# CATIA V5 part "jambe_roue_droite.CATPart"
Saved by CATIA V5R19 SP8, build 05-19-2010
Part number: jambe_roue_droite
Bounding box of the stored display mesh (mm): x 615 to 975, y -524.989 to 900, z -644.15 to 166.768
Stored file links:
  G:\EU_thinkMotion\CFAO_2010\MMS_groupe2\MMS_groupe2\OK\mmartini\mmartiniCFAO\jambe_roue_droite.CATPart
  C:\Users\Mathieu Martini\Desktop\CFAO\Animation\CFAO.CATProduct
  G:\EU_thinkMotion\CFAO_2010\MMS_groupe2\MMS_groupe2\OK\mmartini\mmartiniCFAO\Squelette.CATPart
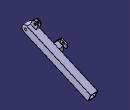
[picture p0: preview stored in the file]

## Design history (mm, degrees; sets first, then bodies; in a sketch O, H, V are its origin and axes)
External parameters (linked from other documents)
  External.diametre_canon = 150 mm
  External.diametre_verin = 120 mm
AxisSystem1: origin (0, 0, 0), X (1, 0, 0), Y (0, 1, 0), Z (0, 0, 1)
Set1
  Sketch1 on Plane1, origin (825, 0, 0), H (0, 1, 0), V (0, 0, 1)
    axis line L1 (-516.747, 29.0949) -> (1500, -850)
    point P2 (1500, -850)
    reference projected point E1 (1500, -850) from Line1
    line L2 (-420.0311, 68.7522) -> (900, -506.646)
    point P3 (900, -506.646)
    reference projected point E2 (-450, 0) from Point2
    circle A1 centre (-450, 0) radius 24
    point P4 (-450, 0)
    reference projected point E3 (-450, 0) from Point2
    line L3 (840.0622, -644.1504) -> (-479.9689, -68.7522)
    point P5 (840.0622, -644.1504)
    arc A2 centre (-450, 0) radius 75 from (-420.0311, 68.7522) to (-479.9689, -68.7522) ccw
    point P6 (-420.0311, 68.7522)
    reference intersected line E4 through (900, 0) direction (0, 1) from Plane2
    line L4 (900, -506.646) -> (840.0622, -644.1504)
    point P9 (840.0622, -644.1504)
    distance L1 L2 = 75 {= External.diametre_canon /2}
    radius A1 = 24 {= External.diametre_verin /5}
    distance L3 L1 = 75 {= External.diametre_canon /2}
    coincidence: P2 E1, L1 E2, P4 E3, A2 P6, P6 L2, P3 E4, P9 L3, P9 P5
    tangency: A2 L2
    perpendicularity: L4 L3
Set2
  Plane1 "Plan_jambe_droite_roue": linked copy from another document
  Point1 "Point_verin_droit": linked copy from another document
  Line1 "axe_roue": linked copy from another document
  Point2: linked copy from another document
  Plane2 "Plan_berceaumax": linked copy from another document
  Plane3: linked copy from another document
  Line2 "Droite_plan_de_construction_verin": linked copy from another document
  Plane4 "Plan_verin_droit": linked copy from another document
  Point3: linked copy from another document
  Plane5: linked copy from another document
  Plane6 "Plan_rayon_ext_verin_droit": linked copy from another document
  Plane7 "Plan_rayon_int_verin_droit": linked copy from another document
  Point4: linked copy from another document
  Line3: linked copy from another document
Body1 (main body)
  Pad1: profile Sketch1, direction (1, 0, 0), length 150 {= External.diametre_canon}
  Line4 "Droite_plan_de_construction_verin": type PtPt, FirstPoint Point3, SecondPoint Point1
  Sketch2 on face of Pad1 from Sketch1.L4, origin (0, 941.8819, -410.5639), H (-1, 0, 0), V (0, 0.3996, 0.9167)
    line L1 (-960, -119.8134) -> (-840, -119.8134)
    line L2 (-840, -119.8134) -> (-840, -239.8134)
    line L3 (-840, -239.8134) -> (-960, -239.8134)
    line L4 (-960, -239.8134) -> (-960, -119.8134)
    reference projected line E1 (-825, -104.8134) -> (-975, -104.8134) from edge [face of Pad1 from Sketch1.L2 | face of Pad1 from Sketch1.L4]
    reference projected line E2 (-825, -254.8134) -> (-825, -104.8134) from edge [start face of Pad1 | face of Pad1 from Sketch1.L4]
    distance L3 L1 = 120 {= External.diametre_verin}
    distance L2 L4 = 120 {= External.diametre_verin}
    distance L1 E1 = 15 {= (External.diametre_canon -External.diametre_verin )/2}
    distance L2 E2 = 15 {= (External.diametre_canon -External.diametre_verin )/2}
    horizontal: L1 H, L3 H
    vertical: L2 V, L4 V
  Pocket1: profile Sketch2, direction (0, -0.9167, 0.3996), up to Plane3
  Sketch3 on Plane3, origin (0, 0, 0), H (-1, 0, 0), V (0, 0, 1)
    line L1 (-825, -160) -> (-615, -160)
    line L2 (-615, -160) -> (-615, -240)
    line L3 (-615, -240) -> (-825, -240)
    line L4 (-825, -240) -> (-825, -160)
    reference intersected line E1 through (-825, 0) direction (0, -1) from Plane1
    reference projected line E2 through (0, -200) direction (-1, 0) from Line2
    reference projected line E3 through (0, -200) direction (-1, 0) from Line2
    distance E2 L1 = 40 {= External.diametre_verin /3}
    distance E3 L3 = 40 {= External.diametre_verin /3}
    distance L2 L4 = 210 {= External.diametre_canon *1.4}
    horizontal: L1 H, L3 H
    vertical: L2 V, L4 V
    coincidence: E1 L4
  Sketch4 on Plane1, origin (825, 0, 0), H (0, 1, 0), V (0, 0, 1)
    projected line E1 (900, -506.646) -> (-420.0311, 68.7522) from edge [start face of Pad1 | face of Pad1 from Sketch1.L2]
    projected line E2 (60, -140.4921) -> (-75, -81.646) from edge [start face of Pad1 | face of Pad1 from Sketch1.L2]
    projected line E3 (-479.9689, -68.7522) -> (840.0622, -644.1504) from edge [start face of Pad1 | face of Pad1 from Sketch1.L3]
    projected line E4 (-75, -245.2771) -> (60, -304.1233) from edge [start face of Pad1 | face of Pad1 from Sketch1.L3]
    line L1 (60, -140.4921) -> (60, -304.1233)
    point P5 (60, -140.4921)
    point P6 (60, -304.1233)
    line L2 (-75, -245.2771) -> (-75, -81.646)
    point P7 (-75, -245.2771)
    point P8 (-75, -81.646)
    reference projected point E5 (0, -200) from Point1
    reference projected point E6 (0, -200) from Point1
    distance E5 L1 = 60 {= External.diametre_verin /2}
    distance L2 E6 = 75 {= External.diametre_canon /2}
    coincidence: P5 E1, P6 E3, P7 E3, P8 E1
    vertical: L1 V, L2 V
  SolidCombine1: FirstComponentProfile Sketch3, FirstComponentDirection edge [start face of Pad1 | face of Pad1 from Sketch1.L3], SecondComponentProfile Sketch4, SecondComponentDirection Sketch4
  Sketch5 on face of SolidCombine1 from Sketch3.L2, origin (615, 0, 0), H (0, -1, 0), V (0, 0, 1)
    circle A1 centre (0, -200) radius 24
    point P1 (0, -200)
    reference projected point E1 (0, -200) from Point1
    radius A1 = 24 {= External.diametre_verin /5}
    coincidence: P1 E1
  Pocket2: profile Sketch5, direction (1, 0, 0), up to Plane1
  Chamfer1: length 30 {= External.diametre_canon /5}, angle 45, on edge [face of SolidCombine1 from Sketch3.L1 | face of SolidCombine1 from Sketch4.L2]
  Sketch6 on Plane5, origin (0, 0, 0), H (1, 0, 0), V (0, 1, 0)
    line L1 (645, 75) -> (705, 75)
    line L2 (705, 75) -> (705, -60)
    line L3 (705, -60) -> (645, -60)
    line L4 (645, -60) -> (645, 75)
    reference intersected line E1 through (735, 0) direction (0, 1) from Plane6
    reference projected line E2 through (0, 0) direction (1, 0) from Line2
    reference projected line E3 through (0, 0) direction (1, 0) from Line2
    reference intersected line E4 through (615, 0) direction (0, 1) from Plane7
    distance L2 E1 = 30 {= External.diametre_canon /5}
    distance E2 L3 = 60 {= External.diametre_verin /2}
    distance E3 L1 = 75 {= External.diametre_canon /2}
    distance L4 E4 = 30 {= External.diametre_canon /5}
    horizontal: L1 H, L3 H
    vertical: L2 V, L4 V
  Pocket3: profile Sketch6, direction (0, 0, -1), up to face of SolidCombine1 from Sketch3.L3
  Sketch7 on face of Pad1 from Sketch1.L2, origin (0, -41.8819, -96.0821), H (-1, 0, 0), V (0, -0.9167, 0.3996)
    line L1 (-900, 412.5132) -> (-825, 412.5132)
    line L2 (-825, 412.5132) -> (-825, 292.5132)
    line L3 (-825, 292.5132) -> (-900, 292.5132)
    line L4 (-900, 292.5132) -> (-900, 412.5132)
    reference projected line E1 (-825, 412.5132) -> (-975, 412.5132) from edge [face of Pad1 from Sketch1.A2 | face of Pad1 from Sketch1.L2]
    reference projected line E2 (-825, -1027.4747) -> (-825, 412.5132) from edge [start face of Pad1 | face of Pad1 from Sketch1.L2]
    distance L2 L4 = 75 {= External.diametre_canon /2}
    distance L1 L3 = 120 {= External.diametre_verin}
    horizontal: L1 H, L3 H
    vertical: L2 V, L4 V
    coincidence: L1 E1, L2 E2
  Pad2: profile Sketch7, direction (0, 0.3996, 0.9167), length 120 {= External.diametre_verin}
  Sketch8 on end face of Pad2, origin (0, 6.0683, 13.9215), H (-1, 0, 0), V (0, -0.9167, 0.3996)
    line L1 (-885, 412.5132) -> (-840, 412.5132)
    line L2 (-840, 412.5132) -> (-840, 292.5132)
    line L3 (-840, 292.5132) -> (-885, 292.5132)
    line L4 (-885, 292.5132) -> (-885, 412.5132)
    reference projected line E1 (-825, 412.5132) -> (-900, 412.5132) from edge [face of Pad2 from Sketch7.L1 | end face of Pad2]
    reference projected line E2 (-900, 292.5132) -> (-825, 292.5132) from edge [face of Pad2 from Sketch7.L3 | end face of Pad2]
    reference projected line E3 (-825, 292.5132) -> (-825, 412.5132) from edge [face of Pad2 from Sketch7.L2 | end face of Pad2]
    reference projected line E4 (-900, 412.5132) -> (-900, 292.5132) from edge [face of Pad2 from Sketch7.L4 | end face of Pad2]
    distance L2 E3 = 15 {= External.diametre_canon /10}
    distance L4 E4 = 15 {= External.diametre_canon /10}
    horizontal: L1 H, L3 H
    vertical: L2 V, L4 V
    coincidence: L1 E1, L3 E2
  Pocket4: profile Sketch8, direction (0, -0.3996, -0.9167), up to face of Pad1 from Sketch1.L2
  Sketch9 on face of Pad2 from Sketch7.L4, origin (900, 0, 0), H (0, 1, 0), V (0, 0, 1)
    axis line L1 (-301.1678, 97.2232) -> (-363.6132, 124.9767)
    reference projected point E1 (-376.0481, 130.5033) from Point4
    reference projected line E2 through (-74.2268, -167.0103) direction (0.9138, -0.4061) from Line3
    circle A1 centre (-330.3575, 110.1964) radius 24
    point P3 (-330.3575, 110.1964)
    reference projected point E3 (-376.0481, 130.5033) from Point4
    distance E3 P3 = 50 {= External.diametre_canon /3}
    radius A1 = 24 {= External.diametre_verin /5}
    coincidence: L1 E1, P3 L1
    parallelism: L1 E2
  Pocket5: profile Sketch9, direction (-1, 0, 0), through (limit type 3)
  Chamfer2: length 30 {= External.diametre_canon /5}, angle 45, on edge [face of Pad2 from Sketch7.L1 | end face of Pad2] (x2); edge [face of Pad2 from Sketch7.L3 | end face of Pad2] (x2)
